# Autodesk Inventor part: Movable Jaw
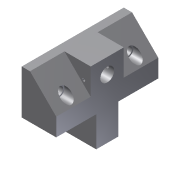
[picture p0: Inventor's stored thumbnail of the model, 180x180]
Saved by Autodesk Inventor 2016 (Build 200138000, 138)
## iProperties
Shininess: 77.0
Length Units: 11269
Angle Units: 11279
Time Units: 11290
Mass Units: 11283
Length Display Precision: 3
Angle Display Precision: 2
Created: 2002-02
Part Number: Movable Jaw
Document SubType Name: Modeling
Designer: ***
Density: 1 g/cm^3
Material: Generic
Appearance: Default
Density: 0.0
Volumn: 0.0
Area: 0.0
PropertySet Name: Model Information
Control State: 0
Master: False
Checked Out: False
Author: ***
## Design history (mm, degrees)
sketch "Sketch2"
  geometry: L1 (2.39, 41.509)-(2.39, 9.509); L2 (2.39, 9.509)-(-22.61, 9.509); L3 (-22.61, 9.509)-(-22.61, 22.509); L4 (-22.61, 22.509)-(-3.61, 41.509); L5 (-3.61, 41.509)-(2.39, 41.509)
  constraints: 10 end point, 2 parallel, 1 perpendicular, 1 vertical
  dimensions: "d0" = 25 distance of L1.end L2.end; "d2" = 13 distance of L2.end L3.end; "d3" = 32 distance between parallel lines of L5 L2; "d4" = 6 distance of L4.end L1.start
extrude "Extrusion1" new body sketch "Sketch2" stored distance "d5" = 74; taper "d6" = 0 deg
sketch "Sketch3"
  geometry: L1 (-19, 25)-(11, 25); L2 (11, 25)-(11, 49); L3 (11, 49)-(-19, 49); L4 (-19, 49)-(-19, 25); L5 (0, 0)-(13, 0) reference; L6 (-19, 74)-(-19, 0) reference; L7 (11.924, 29)-(35, 29); L8 (35, 29)-(35, 45); L9 (35, 45)-(11.924, 45); L10 (11.924, 45)-(11.924, 29); L11 (13, 74)-(13, 0) reference
  constraints: 16 end point, 4 parallel, 2 horizontal, 2 perpendicular, 1 collinear
  dimensions: "d7" = 24 distance of L3.end L1.start; "d8" = 30 distance of L1.start L1.end; "d9" = 25 distance between parallel lines of L5 L1; "d10" = 16 distance of L7.end L8.end; "d11" = 4 distance between parallel lines of L3 L9; "d12" = 22 distance between parallel lines of L11 L8
extrude "Extrusion2" join sketch "Sketch3" distance "d13" = 25; taper "d14" = 0 deg
sketch "Sketch4"
  geometry: L1 (-19, -25)-(-19, -49) reference; L2 (-19, -49)-(0, -49) reference; 1 further point
  dimensions: "d15" = 11 distance from line of L1 point (-8, -37); "d16" = 12 distance from line of L2 point (-8, -37)
hole "Hole1" sketch "Sketch4" at (-8, -37) diameter "d17" = 10; stored, may be unused: countersink angle "d21" = 82 deg, drill point angle "d23" = 0 deg; dims "d18" = 6, "d19" = 4, "d20" = 2, "d22" = 13
sketch "Sketch5"
  geometry: L1 (-19, -49)-(-19, -74) reference; L2 (0, -74)-(13, -74) reference; 1 further point
  dimensions: "d24" = 14 distance from line of L1 point (-5, -62); "d25" = 12 distance from line of L2 point (-5, -62)
hole "Hole2" sketch "Sketch5" at (-5, -62) diameter "d26" = 6; stored, may be unused: countersink angle "d30" = 82 deg, drill point angle "d32" = 0 deg; dims "d27" = 6, "d28" = 8, "d29" = 10, "d31" = 13
mirror "Mirror1"
sketch "Sketch6"
  geometry: L1 (0, 19)-(0, 0) reference; 1 further point
  dimensions: "d33" = 5 distance from line of L1 point (-5, 8); "d34" = 11 vertical distance of L1.start point (-5, 8)
hole "Hole3" sketch "Sketch6" at (-5, 8) diameter "d35" = 2; stored, may be unused: countersink angle "d39" = 82 deg, drill point angle "d41" = 0 deg; dims "d36" = 6, "d37" = 8, "d38" = 10, "d40" = 13
body "Solid1"
